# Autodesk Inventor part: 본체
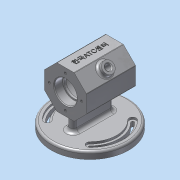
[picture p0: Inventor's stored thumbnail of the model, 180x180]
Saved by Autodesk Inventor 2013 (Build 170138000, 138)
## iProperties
Created: 2017-06
Part Number: 본체
Material: 알루미늄 6061
Document SubType Name: Modeling
Designer: dgall
Density: 2.71 g/cm^3
Mass: 562.266 g
Surface Area: 566.116 cm^2
Volume: 207.478 cm^3
Author: dgall
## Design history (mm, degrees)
sketch "스케치1"
  geometry: L1 (-30, 12.426)-(-12.426, 30); L2 (-12.426, 30)-(12.426, 30); L3 (12.426, 30)-(30, 12.426); L4 (30, 12.426)-(30, -12.426); L5 (30, -12.426)-(12.426, -30); L6 (12.426, -30)-(-12.426, -30); L7 (-12.426, -30)-(-30, -12.426); L8 (-30, -12.426)-(-30, 12.426); 3 further points
  constraints: 16 end point, 1 coincident, 1 horizontal alignment, 1 midpoint, 17 other
  dimensions: "d1" = 30 distance from line of L8 point (0, 0)
extrude "돌출1" new body sketch "스케치1" distance "d2" = 70; taper "d3" = 0 deg
sketch "스케치2"
  geometry: L1 (30, 0)-(30, 70) reference; L2 (30, 70)-(12.426, 70) reference; L3 (12.426, 70)-(-12.426, 70) reference; L4 (-12.426, 70)-(-30, 70) reference; L5 (-30, 0)-(-30, 70) reference; L6 (-30, 0)-(-12.426, 0) reference; L7 (-12.426, 0)-(12.426, 0) reference; L8 (12.426, 0)-(30, 0) reference; L9 (0, 0)-(0, 70); L10 (16, 70)-(16, 58); L11 (16, 58)-(14, 58); L12 (14, 58)-(14, 55); L13 (14, 55)-(25, 55); L14 (25, 55)-(25, 15); L15 (25, 15)-(14, 15); L16 (14, 15)-(14, 12); L17 (14, 12)-(16, 12); L18 (16, 12)-(16, 0); L19 (16, 0)-(0, 0); L20 (16, 70)-(0, 70)
  constraints: 24 end point, 7 parallel, 2 collinear, 2 perpendicular, 2 point on line, 1 midpoint
  dimensions: "d4" = 12 distance of L10.start L10.end; "d6" = 32 diameter of L10 L9; "d7" = 3 distance of L11.end L12.end; "d8" = 28 diameter of L12 L9; "d9" = 40 distance of L13.end L14.end; "d10" = 50 diameter of L14 L9; "d11" = 3 distance of L15.end L16.end; "d12" = 28 diameter of L16 L9; "d13" = 32 diameter of L18 L9
revolve "회전1" sketch "스케치2" stored, may be unused: angle "d14" = 90 deg
fillet "모깎기1" dims "d15" = 0.3, "d16" = 3
chamfer "모따기1" distance "d17" = 1; stored, may be unused: second distance "d18" = 2, angle "d19" = 45 deg
sketch "스케치3"
  geometry: C1 r 17 at (0, 0) reference; 1 further point
  constraints: 1 vertical alignment
  dimensions: "d20" = 23 distance of C1.centre point (0, 23)
hole "구멍1" sketch "스케치3" at (0, 23) diameter "d21" = 3.459; stored, may be unused: countersink angle "d25" = 90 deg, drill point angle "d27" = 118 deg; dims "d22" = 8, "d23" = 4, "d24" = 2, "d26" = 10
node "작업 평면1"
node "작업 평면2"
sketch "스케치4"
  geometry: L1 (-30, 70)-(-12.426, 70) reference; L2 (-12.426, 70)-(12.426, 70) reference; L3 (12.426, 70)-(30, 70) reference; L4 (30, 0)-(30, 70) reference; L5 (-30, 0)-(-30, 70) reference; L6 (12.426, 0)-(-12.426, 0) reference; L7 (-12.426, 0)-(-30, 0) reference; L8 (30, 0)-(12.426, 0) reference; C1 r 55 at (0, 35); 3 further points
  constraints: 2 midpoint, 1 centre point, 1 horizontal alignment, 1 vertical alignment
  dimensions: "d32" = 110 diameter of C1
extrude "돌출2" join sketch "스케치4" distance "d33" = 10; taper "d34" = 0 deg
sketch "스케치5"
  geometry: L1 (-5, -24)-(-5, 24); L2 (5, 24)-(5, -24); C1 r 55 at (0, 0) reference; A1 r 5 centre (0, 24) between (5, 24) and (-5, 24); A2 r 5 centre (0, -24) between (-5, -24) and (5, -24); 3 further points
  constraints: 5 point on circle, 4 end point, 4 tangent, 2 centre point, 1 horizontal alignment, 1 midpoint, 1 parallel, 1 vertical, 1 vertical alignment
  dimensions: "d35" = 48 distance of A1.centre A2.centre; "d37" = 5 radius of A1
extrude "돌출3" join sketch "스케치5" stored distance "d38" = 10; taper "d39" = 0 deg
fillet "모깎기2" dims "d40" = 5
sketch "스케치6"
  geometry: L1 (-10, 24)-(-10, -24) reference; L2 (0, 0)-(-45.465, 45.465); L3 (0, 0)-(-47.277, -47.277); L4 (0, 0)-(-63.704, 0); C1 r 55 at (0, 0) reference; C2 r 43 at (0, 0); A1 r 38 centre (0, 0) between (-26.87, -26.87) and (-26.87, 26.87); A2 r 48 centre (0, 0) between (-33.941, -33.941) and (-33.941, 33.941); A3 r 5 centre (-30.406, -30.406) between (-33.941, -33.941) and (-26.87, -26.87); A4 r 5 centre (-30.406, 30.406) between (-26.87, 26.87) and (-33.941, 33.941); A5 r 48 centre (0, 0) between (-33.941, 33.941) and (-33.941, -33.941); A6 r 38 centre (0, 0) between (-26.87, 26.87) and (-26.87, -26.87); A7 r 2 centre (-30.406, -30.406) between (-31.82, -31.82) and (-28.991, -28.991); A8 r 2 centre (-30.406, 30.406) between (-28.991, 28.991) and (-31.82, 31.82); A9 r 41 centre (0, 0) between (-28.991, 28.991) and (-28.991, -28.991); A10 r 45 centre (0, 0) between (-31.82, 31.82) and (-31.82, -31.82); 1 further point
  constraints: 24 point on circle, 11 centre point, 8 point on line, 6 end point, 4 tangent, 3 coincident, 1 perpendicular
  dimensions: "d41" = 86 diameter of C2; "d42" = 90 deg angle of L2 L3; "d44" = 76 diameter of A1; "d45" = 96 diameter of A2; "d46" = 45 deg angle of L3 L4; "d47" = 5 radius of A3; "d48" = 5 radius of A4; "d49" = 2 radius of A7; "d50" = 2 radius of A8
extrude "돌출4" cut sketch "스케치6" distance "d51" = 3; taper "d52" = 0 deg
extrude "돌출5" cut sketch "스케치6" distance "d53" = 10; taper "d54" = 0 deg
fillet "모깎기3" dims "d55" = 3
sketch "스케치7"
  geometry: L1 (0, 0)-(-24.853, 0) reference; L2 (-24.853, 70)-(0, 70) reference; C1 r 8 at (-12.426, 35); C2 r 4 at (-12.426, 35); 2 further points
  constraints: 2 centre point, 1 coincident, 1 midpoint, 1 vertical alignment
  dimensions: "d56" = 16 diameter of C1; "d57" = 8 diameter of C2; "d58" = 35 distance from line of L2 C2.centre
extrude "돌출6" join sketch "스케치7" distance "d59" = 7; taper "d60" = 0 deg
extrude "돌출7" cut sketch "스케치7" stored distance "d61" = 7; taper "d62" = 0 deg
fillet "모깎기4" dims "d63" = 3
chamfer "모따기2" distance "d64" = 1; stored, may be unused: second distance "d65" = 2, angle "d66" = 45 deg
sketch "스케치8"
  geometry: L1 (24.853, -70)-(0, -70) reference; L2 (-17.574, 0)-(-17.574, -70) reference; 2 further points
  constraints: 1 other
  dimensions: "d67" = 35 distance from line of L1 point (12.426, -35); "d68" = 30 distance from line of L2 point (12.426, -35)
feature "엠보싱1" sketch "스케치8" dims "d69" = 0.5, "d70" = 0
fillet "모깎기5" dims "d71" = 1
node "솔리드1"
pattern_circular "원형 패턴1" dims angle "d29" = 360 deg
mirror "대칭1"
mirror "대칭2"
other parameters: "d31" = -62
